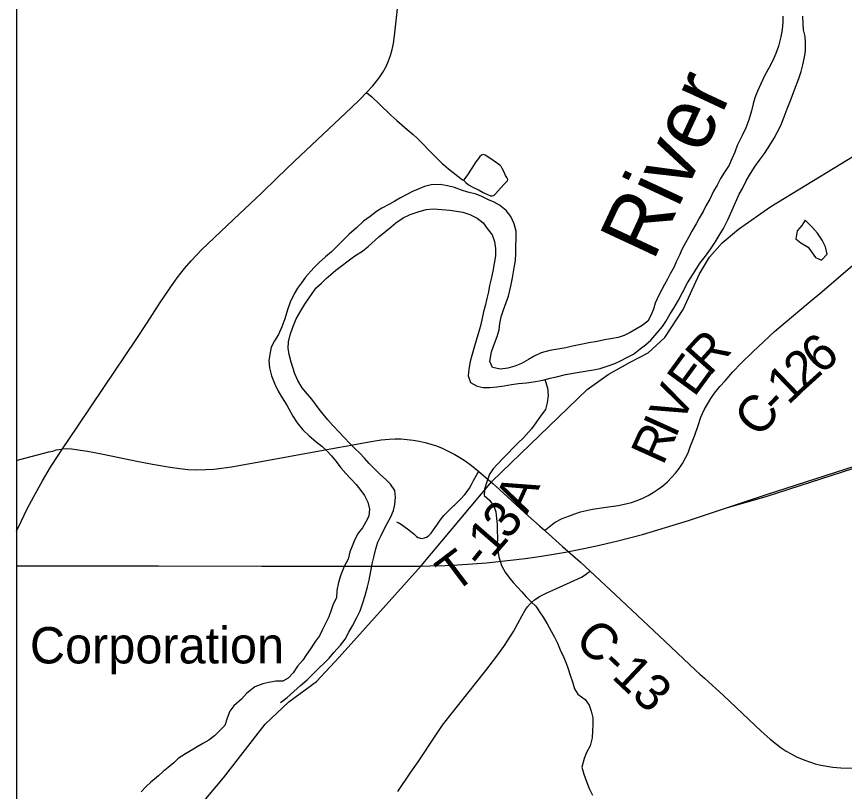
# Model space of a CAD drawing. Extents: x 0 to 34, y 0 to 22.
# Drawn here: x 2.1 to 3.389, y 14.854 to 16.061 of the extents above; entities that cross this region are included whole.
import ezdxf

# ---------------------------------------------------------------- set-up
doc = ezdxf.new("R2010")
doc.units = 0
for name, color, linetype in [('GM_X_Corporation', 7, 'Continuous'), ('GM_X_County_Road', 7, 'Continuous'), ('GM_X_County_Road_Text', 7, 'Continuous'), ('GM_X_Major_River', 7, 'Continuous'), ('GM_X_Minor_Lake', 7, 'Continuous'), ('GM_X_Minor_River', 7, 'Continuous'), ('GM_X_Minor_River_Text', 7, 'Continuous'), ('GM_X_Rail_Line', 7, 'Continuous'), ('GM_X_Rail_Line_Text', 7, 'Continuous'), ('GM_X_State_Route', 7, 'Continuous'), ('GM_X_Township_Road', 7, 'Continuous'), ('GM_X_Township_Road_Text', 7, 'Continuous'), ('SH_Data', 7, 'Continuous')]:
    doc.layers.add(name, color=color, linetype=linetype)

msp = doc.modelspace()

# ---------------------------------------------------------------- linework, layer by layer
at = {"layer": 'GM_X_Corporation'}
for points in [[(2.1, 20.7089), (2.1, 14.1)], [(2.1, 16.8894), (2.1, 14.1)]]:
    msp.add_lwpolyline(points, dxfattribs=at)
at = {"layer": 'GM_X_County_Road'}
for points in [[(3.161, 15.4241), (3.1655, 15.4373), (3.1705, 15.4485), (3.1761, 15.4586), (3.1811, 15.4662), (3.1867, 15.4748), (3.1948, 15.4849), (3.2031, 15.494), (3.2153, 15.508), (3.2282, 15.5214), (3.2461, 15.5387), (3.2801, 15.5704), (3.2965, 15.5846), (3.3322, 15.6145), (3.3537, 15.6322), (3.4055, 15.6768)], [(2.9221, 15.2611), (2.9238, 15.2624), (2.9342, 15.2704), (2.9387, 15.2736), (2.9495, 15.2794), (2.9606, 15.2834), (2.9693, 15.2868), (2.9782, 15.2897), (2.9873, 15.292), (2.9965, 15.2938), (3.018, 15.297), (3.0364, 15.2997), (3.0486, 15.3021), (3.0575, 15.3045), (3.0663, 15.3075), (3.0748, 15.3111), (3.0831, 15.3152), (3.0911, 15.3198), (3.0989, 15.3249), (3.1062, 15.3305), (3.1132, 15.3366), (3.1198, 15.343), (3.1261, 15.3499), (3.1318, 15.3571), (3.1366, 15.365), (3.1417, 15.3741), (3.1457, 15.3817), (3.1488, 15.3908), (3.1559, 15.409), (3.161, 15.4241)], [(2.1717, 15.3879), (2.1783, 15.3883), (2.1856, 15.3878), (2.2106, 15.3842), (2.2321, 15.3802), (2.29, 15.3681), (2.3114, 15.3639), (2.3389, 15.3591), (2.3543, 15.357), (2.3667, 15.3558), (2.3791, 15.3553), (2.3946, 15.3556), (2.4069, 15.3563), (2.4193, 15.3576), (2.4346, 15.3599), (2.4867, 15.3692), (2.5602, 15.3826), (2.6521, 15.3994), (2.6676, 15.4017), (2.68, 15.4029), (2.6894, 15.4033), (2.6988, 15.4032), (2.7081, 15.4025), (2.7175, 15.4014), (2.7267, 15.3998), (2.7359, 15.3978), (2.7449, 15.3953), (2.7539, 15.3923), (2.7626, 15.3889), (2.7711, 15.385), (2.7823, 15.3792), (2.7903, 15.3745), (2.7982, 15.3693), (2.8082, 15.3618), (2.8195, 15.3526)], [(2.1, 15.3698), (2.1053, 15.3713), (2.1503, 15.3833), (2.1565, 15.3845), (2.1617, 15.3861), (2.17, 15.3876), (2.1717, 15.3879)], [(2.8195, 15.3526), (2.8203, 15.352), (2.8416, 15.3337), (2.8462, 15.3296), (2.8967, 15.2834), (2.9144, 15.2682), (2.9221, 15.2611)], [(2.9221, 15.2611), (2.9235, 15.2599), (2.9499, 15.2356), (2.9779, 15.2112), (2.993, 15.1972)], [(2.993, 15.1972), (3.0325, 15.1605), (3.1005, 15.0966), (3.1571, 15.0433), (3.1636, 15.0368), (3.1708, 15.0309), (3.2006, 15.0037), (3.2595, 14.9483), (3.2734, 14.9358), (3.2829, 14.9279), (3.2904, 14.9224), (3.2982, 14.9173), (3.3062, 14.9127), (3.3145, 14.9085), (3.3258, 14.9035), (3.3345, 14.9003), (3.3434, 14.8976), (3.3524, 14.8954), (3.3615, 14.8936), (3.3707, 14.8923), (3.3831, 14.8913), (3.4048, 14.8905)]]:
    msp.add_lwpolyline(points, dxfattribs=at)
at = {"layer": 'GM_X_Major_River'}
for points in [[(2.8346, 15.6325), (2.832, 15.6222), (2.8294, 15.6108), (2.8272, 15.6012), (2.825, 15.5913), (2.8228, 15.5814), (2.8202, 15.5723), (2.8164, 15.5601), (2.812, 15.5441), (2.8087, 15.5334), (2.8061, 15.5239), (2.8039, 15.5121), (2.8032, 15.5015), (2.8067, 15.4912), (2.817, 15.4856), (2.8265, 15.4834), (2.8367, 15.4834), (2.8477, 15.4843), (2.8591, 15.4859), (2.8705, 15.4878), (2.8815, 15.4894), (2.8937, 15.4906), (2.9081, 15.4926), (2.9195, 15.495), (2.9308, 15.4981), (2.9426, 15.5005), (2.9547, 15.5036), (2.976, 15.5075), (2.9885, 15.5091), (2.998, 15.5107), (3.0086, 15.513), (3.0211, 15.5169), (3.0313, 15.5208), (3.0404, 15.525), (3.0514, 15.5304), (3.0605, 15.5354), (3.0707, 15.5435), (3.0794, 15.5496), (3.0877, 15.5569), (3.0967, 15.568), (3.1054, 15.5783), (3.1107, 15.5863), (3.1174, 15.5981), (3.1231, 15.6069), (3.1306, 15.6195), (3.1369, 15.6313), (3.1444, 15.6462), (3.1531, 15.6592), (3.1644, 15.6775), (3.1726, 15.6878), (3.1802, 15.6989), (3.1877, 15.7096), (3.1941, 15.7199), (3.2005, 15.731), (3.208, 15.7455), (3.2136, 15.7584), (3.2192, 15.7714), (3.2248, 15.7844), (3.23, 15.7931), (3.236, 15.805), (3.2424, 15.8164), (3.2499, 15.8282), (3.2567, 15.8374), (3.2642, 15.8477), (3.2729, 15.8607), (3.2796, 15.8718), (3.2849, 15.8813), (3.2898, 15.8916), (3.295, 15.9046), (3.2998, 15.9175), (3.3062, 15.9328), (3.311, 15.9469), (3.3177, 15.9648), (3.3215, 15.9754), (3.3241, 15.9857), (3.3266, 15.9979), (3.3281, 16.0078), (3.3284, 16.02), (3.3279, 16.0299), (3.3252, 16.0401), (3.3244, 16.0504), (3.3243, 16.0618)], [(3.2931, 16.0616), (3.2932, 16.0521), (3.2921, 16.041), (3.2899, 16.0292), (3.2862, 16.0151), (3.2821, 16.0037), (3.2773, 15.9926), (3.2717, 15.9816), (3.2649, 15.9698), (3.2585, 15.9564), (3.2533, 15.945), (3.2492, 15.9343), (3.2466, 15.9252), (3.2444, 15.9141), (3.2399, 15.9), (3.2355, 15.8878), (3.2295, 15.876), (3.222, 15.8604), (3.2182, 15.8497), (3.2138, 15.8394), (3.2093, 15.8295), (3.2021, 15.8188), (3.1961, 15.8089), (3.1905, 15.7986), (3.1852, 15.789), (3.1792, 15.7765), (3.1732, 15.7665), (3.1687, 15.7574), (3.1627, 15.7471), (3.1582, 15.7383), (3.1511, 15.7269), (3.1459, 15.7169), (3.1414, 15.7085), (3.1365, 15.6994), (3.132, 15.6895), (3.1275, 15.6803), (3.1238, 15.6712), (3.1178, 15.6605), (3.1133, 15.6521), (3.1088, 15.6437), (3.1005, 15.6284), (3.0941, 15.6147), (3.0915, 15.6052), (3.0874, 15.5953), (3.0826, 15.5869), (3.0742, 15.58), (3.0652, 15.5746), (3.0553, 15.5692), (3.0459, 15.5646), (3.0364, 15.5615), (3.0246, 15.5591), (3.0151, 15.5576), (3.0041, 15.5552), (2.9912, 15.5529)], [(2.9912, 15.5529), (2.9783, 15.5505), (2.9654, 15.5477), (2.9552, 15.5454), (2.9396, 15.5426), (2.9302, 15.5411), (2.9169, 15.5372), (2.9059, 15.5322), (2.8972, 15.5268), (2.8859, 15.5206), (2.8756, 15.5164), (2.865, 15.5133), (2.8532, 15.5117), (2.8411, 15.5146), (2.8368, 15.5237), (2.8394, 15.539), (2.8439, 15.5519), (2.8483, 15.563), (2.8513, 15.5733), (2.8524, 15.5828), (2.8546, 15.5934), (2.8579, 15.6045), (2.862, 15.6159), (2.8658, 15.6254), (2.8694, 15.641), (2.872, 15.6544), (2.8749, 15.6696), (2.8768, 15.6814), (2.8775, 15.692), (2.8774, 15.7035), (2.8777, 15.7156), (2.8776, 15.727), (2.8749, 15.7384), (2.8695, 15.7494), (2.8622, 15.7589), (2.8519, 15.7672), (2.8435, 15.7721), (2.8347, 15.7758), (2.8244, 15.7807), (2.8153, 15.7844), (2.8027, 15.7878), (2.7928, 15.7907), (2.7818, 15.7949), (2.7711, 15.7974), (2.7593, 15.7993), (2.7453, 15.7992), (2.735, 15.7965), (2.7252, 15.7922), (2.7165, 15.7884), (2.7078, 15.7841), (2.6979, 15.7787), (2.6888, 15.7734), (2.6805, 15.7687), (2.6688, 15.7626), (2.6605, 15.7576), (2.6503, 15.7499), (2.6404, 15.7422), (2.6291, 15.7319), (2.6178, 15.722), (2.6076, 15.712), (2.5985, 15.7028), (2.5902, 15.6948), (2.5808, 15.6871), (2.571, 15.6779), (2.5627, 15.6699), (2.5499, 15.655), (2.5435, 15.6466), (2.5374, 15.6382), (2.5322, 15.629), (2.5262, 15.6161), (2.5217, 15.6042), (2.5176, 15.5901), (2.5132, 15.5776), (2.5079, 15.5661), (2.5015, 15.5562), (2.4963, 15.5463), (2.4941, 15.5349), (2.493, 15.5254), (2.4939, 15.514), (2.497, 15.5018), (2.502, 15.4885), (2.5074, 15.4775), (2.5136, 15.4673), (2.5209, 15.456), (2.5301, 15.4389), (2.537, 15.4283), (2.5458, 15.4173), (2.5558, 15.4083), (2.5661, 15.3992), (2.5752, 15.3921), (2.5833, 15.3849), (2.5902, 15.3769), (2.5974, 15.3679), (2.6051, 15.3584), (2.6128, 15.3497), (2.62, 15.3418), (2.6288, 15.3323), (2.6361, 15.3229), (2.6419, 15.3153), (2.6469, 15.3047), (2.6496, 15.2937)], [(2.5111, 14.9928), (2.5213, 15.0009), (2.5315, 15.0101), (2.5421, 15.0193), (2.5523, 15.0284), (2.5617, 15.0376), (2.5719, 15.0472), (2.5787, 15.0541), (2.5866, 15.0617), (2.5942, 15.0705), (2.6044, 15.082), (2.6115, 15.0916), (2.6175, 15.1022), (2.6231, 15.1122), (2.6295, 15.1244), (2.6348, 15.1358), (2.6392, 15.148), (2.6429, 15.1594), (2.6463, 15.1728), (2.6489, 15.1834), (2.6514, 15.1975), (2.654, 15.2108), (2.6566, 15.2215), (2.6595, 15.2321), (2.6625, 15.2424), (2.6674, 15.2527), (2.6722, 15.2626), (2.6771, 15.2718), (2.6827, 15.2821), (2.6869, 15.2916), (2.6891, 15.3012), (2.6901, 15.3126), (2.6889, 15.3228), (2.682, 15.3327), (2.6744, 15.3406), (2.6656, 15.3485), (2.656, 15.358), (2.6491, 15.3648), (2.6415, 15.3731), (2.6342, 15.381), (2.6269, 15.3886), (2.6185, 15.3969), (2.6105, 15.4052), (2.6024, 15.4139), (2.5925, 15.4241), (2.5845, 15.4332), (2.5776, 15.4419), (2.571, 15.4498), (2.5653, 15.4574), (2.5595, 15.4653), (2.553, 15.4729), (2.5446, 15.4831), (2.5381, 15.4941), (2.5334, 15.5047), (2.5276, 15.5229), (2.5245, 15.5347), (2.5229, 15.5446), (2.5236, 15.5544), (2.5262, 15.5655), (2.5299, 15.5773), (2.5355, 15.5903), (2.5426, 15.6029), (2.5486, 15.6132), (2.5543, 15.6216), (2.5603, 15.6296), (2.5667, 15.6384), (2.5746, 15.6456), (2.5818, 15.6529), (2.5893, 15.6594), (2.5973, 15.6659), (2.6056, 15.6725), (2.6162, 15.6805), (2.6268, 15.6882), (2.6385, 15.6959), (2.6472, 15.7028), (2.6642, 15.7181), (2.6747, 15.7269), (2.683, 15.7338), (2.6906, 15.7399), (2.7019, 15.7476), (2.7129, 15.753), (2.7254, 15.7569), (2.7376, 15.7604), (2.7486, 15.7616), (2.7619, 15.7605), (2.7744, 15.7594), (2.7847, 15.758), (2.795, 15.7562), (2.8056, 15.7528), (2.817, 15.7472), (2.8262, 15.7396), (2.8327, 15.7309), (2.8404, 15.7211), (2.8443, 15.7105), (2.8459, 15.6998), (2.8459, 15.6884), (2.8437, 15.6766), (2.8416, 15.6644), (2.839, 15.6526), (2.8364, 15.642), (2.8346, 15.6325)], [(2.6496, 15.2937), (2.6486, 15.283), (2.6437, 15.2743), (2.6384, 15.2647), (2.6316, 15.2563), (2.6264, 15.2468), (2.6227, 15.2365), (2.6189, 15.2277), (2.6163, 15.2163), (2.6103, 15.2045), (2.6051, 15.1915), (2.601, 15.1797), (2.5988, 15.1675), (2.5981, 15.1561), (2.5929, 15.1458), (2.5899, 15.1367), (2.5862, 15.1264), (2.5809, 15.1161), (2.5761, 15.1065), (2.5716, 15.0966), (2.5652, 15.0886), (2.5577, 15.0764), (2.5516, 15.0676), (2.5456, 15.0588), (2.5373, 15.0493), (2.5306, 15.0393), (2.523, 15.0309), (2.5143, 15.0263), (2.5037, 15.0259), (2.4927, 15.0239), (2.4832, 15.0219), (2.4711, 15.0173), (2.4579, 15.0069), (2.4503, 14.9981), (2.4382, 14.9878), (2.4318, 14.9794), (2.4277, 14.9687), (2.4244, 14.9569), (2.415, 14.9477), (2.4082, 14.9408), (2.3991, 14.9343), (2.3908, 14.9293), (2.3813, 14.924), (2.3719, 14.9182), (2.3628, 14.9128), (2.3518, 14.9059), (2.345, 14.899), (2.3359, 14.8917), (2.3284, 14.8852), (2.3212, 14.8787), (2.3088, 14.8687), (2.302, 14.8619), (2.294, 14.8538)]]:
    msp.add_lwpolyline(points, dxfattribs=at)
at = {"layer": 'GM_X_Minor_Lake'}
for points in [[(3.3276, 15.7439), (3.3227, 15.7355), (3.3152, 15.7271), (3.3134, 15.715), (3.321, 15.7085), (3.3322, 15.7019)], [(3.3322, 15.7019), (3.3378, 15.6946), (3.344, 15.6859), (3.3531, 15.6817), (3.3618, 15.6909), (3.3594, 15.7023), (3.3541, 15.7126), (3.3471, 15.7239), (3.3391, 15.7326), (3.3276, 15.7439)]]:
    msp.add_lwpolyline(points, dxfattribs=at)
at = {"layer": 'GM_X_Minor_River'}
msp.add_lwpolyline([(2.9222, 15.4958), (2.9264, 15.4829), (2.9276, 15.4711), (2.9262, 15.4597), (2.9236, 15.449), (2.9168, 15.4402), (2.9085, 15.4284), (2.9018, 15.4188), (2.8893, 15.4051), (2.881, 15.397), (2.8727, 15.389), (2.8652, 15.3813), (2.858, 15.3741), (2.8486, 15.3641), (2.8418, 15.3565), (2.8361, 15.3485), (2.832, 15.3367), (2.8287, 15.3249), (2.828, 15.3153), (2.8364, 15.3078), (2.8433, 15.2987), (2.8464, 15.2896), (2.8473, 15.2793), (2.8481, 15.2698), (2.8481, 15.26), (2.8486, 15.2497), (2.8483, 15.2391), (2.8491, 15.2296), (2.8507, 15.2197), (2.855, 15.206), (2.8607, 15.1958), (2.8665, 15.1878), (2.8734, 15.1795), (2.8799, 15.1723), (2.8868, 15.1652), (2.8933, 15.1576), (2.901, 15.1497), (2.9082, 15.1429), (2.9144, 15.1342), (2.9201, 15.1255), (2.9263, 15.1156), (2.9324, 15.1042), (2.9374, 15.0948), (2.9424, 15.0853), (2.9463, 15.0747), (2.9513, 15.0641), (2.9556, 15.0542), (2.9587, 15.0451), (2.9618, 15.0352), (2.9653, 15.025), (2.9687, 15.0144), (2.9737, 15.0057), (2.9852, 14.9974), (2.9913, 14.9887), (2.9948, 14.9792), (2.9972, 14.9689), (2.9972, 14.9583), (2.9969, 14.9488), (2.9959, 14.9381), (2.9929, 14.9252), (2.9873, 14.9149), (2.9839, 14.9057), (2.9798, 14.892), (2.983, 14.8814), (2.9872, 14.87), (2.9915, 14.859), (2.9965, 14.8488)], dxfattribs=at)
at = {"layer": 'GM_X_Rail_Line'}
for points in [[(2.7297, 15.2056), (2.8397, 15.3372), (2.9885, 15.4804), (3.0212, 15.5034), (3.0552, 15.5228), (3.0833, 15.5374), (3.1093, 15.5614), (3.1376, 15.6046), (3.1635, 15.6602), (3.1788, 15.6862), (3.1987, 15.7084), (3.224, 15.7301), (3.2743, 15.765), (3.5468, 15.9313), (3.5769, 15.9577), (3.6509, 16.0195), (3.6692, 16.0362), (3.6936, 16.0627)], [(3.2088, 15.2971), (3.2684, 15.3142), (3.4536, 15.3739), (3.5291, 15.3985), (3.8359, 15.4986), (4.0815, 15.5782), (4.2209, 15.6235), (4.4575, 15.6975), (4.6896, 15.7766), (4.9157, 15.8481), (5.2297, 15.9517), (5.4604, 16.0265), (5.5567, 16.0607)], [(2.1, 15.2057), (2.3212, 15.2055), (2.4818, 15.2052), (2.7299, 15.2051), (2.7433, 15.2055), (2.7673, 15.2064), (2.7866, 15.2072), (2.8099, 15.2088), (2.8318, 15.2105), (2.8688, 15.2143), (2.8917, 15.2171), (2.9174, 15.2209), (2.9545, 15.227), (2.9856, 15.2332), (3.0077, 15.2379), (3.0362, 15.2445), (3.0743, 15.2545), (3.1463, 15.2765), (3.2677, 15.3166), (3.4529, 15.3763)], [(2.2464, 14.1), (2.2668, 14.1719), (2.2701, 14.2246), (2.2577, 14.2692), (2.243, 14.3024), (2.2171, 14.3346), (2.1851, 14.3637), (2.1516, 14.3933), (2.1319, 14.4344), (2.1227, 14.467), (2.1207, 14.5129), (2.1301, 14.5585), (2.1526, 14.5946), (2.1807, 14.6303), (2.2177, 14.682), (2.2745, 14.7402), (2.3385, 14.787), (2.3897, 14.8368), (2.4224, 14.8755), (2.4871, 14.9592), (2.5237, 14.9937), (2.567, 15.0258), (2.6022, 15.0634), (2.7297, 15.2056)]]:
    msp.add_lwpolyline(points, dxfattribs=at)
at = {"layer": 'GM_X_State_Route'}
msp.add_lwpolyline([(2.1, 15.2598), (2.1071, 15.2749), (2.1166, 15.2944), (2.1267, 15.3137), (2.1404, 15.3381), (2.1531, 15.3594), (2.1648, 15.3777), (2.1717, 15.3879), (2.1944, 15.4215), (2.236, 15.4835), (2.2862, 15.5583), (2.3034, 15.5843), (2.3238, 15.6155), (2.3394, 15.6387), (2.3503, 15.6539), (2.3617, 15.6686), (2.3716, 15.6805), (2.3799, 15.6896), (2.3887, 15.6984), (2.4473, 15.754), (2.4811, 15.7862), (2.5059, 15.8098), (2.5329, 15.8356), (2.5508, 15.8528), (2.6207, 15.9191), (2.6342, 15.9321), (2.6447, 15.9426), (2.6547, 15.9531), (2.6608, 15.9608), (2.6656, 15.9671), (2.6706, 15.975), (2.6752, 15.9833), (2.679, 15.9918), (2.6822, 16.0006), (2.6847, 16.0096), (2.6867, 16.0188), (2.6885, 16.0311), (2.6984, 16.1208)], dxfattribs=at)
at = {"layer": 'GM_X_Township_Road'}
for points in [[(2.6447, 15.9426), (2.6529, 15.9359), (2.665, 15.9246), (2.6828, 15.9074), (2.6919, 15.8993), (2.7081, 15.885), (2.7173, 15.8776), (2.7242, 15.8712), (2.735, 15.86), (2.7394, 15.8553), (2.7573, 15.8376), (2.7633, 15.8319), (2.7652, 15.8303), (2.7724, 15.8239), (2.7945, 15.807), (2.796, 15.806)], [(2.8646, 15.8075), (2.8633, 15.8105), (2.8612, 15.8136), (2.859, 15.8187), (2.8561, 15.8246), (2.8544, 15.8276), (2.8525, 15.8297), (2.849, 15.8324), (2.8434, 15.8357), (2.8323, 15.8437), (2.8296, 15.8454), (2.8267, 15.846), (2.8237, 15.8453), (2.8214, 15.8433), (2.8192, 15.8402), (2.8151, 15.8346), (2.8089, 15.8251), (2.8008, 15.8131), (2.796, 15.806)], [(2.796, 15.806), (2.7994, 15.8026), (2.8037, 15.7991), (2.8105, 15.7952), (2.8202, 15.7905), (2.8266, 15.7871), (2.8377, 15.7821), (2.8406, 15.7816), (2.8431, 15.7824), (2.8454, 15.7847), (2.8534, 15.7938), (2.8597, 15.8006), (2.8642, 15.805), (2.8646, 15.8075)], [(2.7818, 15.3003), (2.7915, 15.3098), (2.7978, 15.3167), (2.8017, 15.3216), (2.8052, 15.3268), (2.8083, 15.3323), (2.8113, 15.3386), (2.8182, 15.3503), (2.8195, 15.3526)], [(2.6916, 15.2743), (2.6942, 15.2732), (2.6968, 15.2717), (2.6992, 15.2701), (2.7087, 15.2634), (2.7183, 15.2557), (2.7225, 15.2515), (2.7252, 15.2497), (2.7284, 15.2487), (2.7317, 15.2485), (2.7349, 15.2491), (2.738, 15.2502), (2.7409, 15.2521), (2.7432, 15.2543), (2.7453, 15.2567), (2.749, 15.2615), (2.7541, 15.2692), (2.7593, 15.2768), (2.7651, 15.284), (2.7693, 15.2884), (2.7804, 15.299), (2.7818, 15.3003)], [(2.6937, 14.8544), (2.7128, 14.8827), (2.725, 14.9007), (2.7526, 14.9421), (2.7633, 14.9574), (2.7745, 14.9723), (2.8306, 15.0429), (2.8477, 15.065), (2.8586, 15.0801), (2.8655, 15.0904), (2.8735, 15.1036), (2.887, 15.1286), (2.892, 15.1366), (2.8957, 15.1417), (2.8996, 15.1464), (2.9017, 15.1486), (2.9064, 15.1527), (2.9089, 15.1545), (2.9142, 15.1579), (2.9254, 15.1636), (2.9396, 15.1701), (2.968, 15.1826), (2.9797, 15.1883), (2.985, 15.1915), (2.9901, 15.1951), (2.993, 15.1972)]]:
    msp.add_lwpolyline(points, dxfattribs=at)
at = {"layer": 'SH_Data'}
msp.add_line((2.1, 20.9), (2.1, 14.1), dxfattribs=at)

# ---------------------------------------------------------------- texts
at = {"layer": 'GM_X_County_Road_Text'}
for s, height, rotation, p in [('R', 0.0568, 48.0414, (3.179, 15.5001)), ('6', 0.0568, 40.6831, (3.3519, 15.502)), ('E', 0.0568, 53.8797, (3.1549, 15.467)), ('2', 0.0568, 42.0936, (3.3262, 15.4787)), ('1', 0.0568, 43.9622, (3.3014, 15.4548)), ('V', 0.0568, 64.8964, (3.1351, 15.4242)), ('C', 0.0568, 51.2122, (3.2572, 15.403)), ('-', 0.0568, 45.977, (3.2855, 15.4384)), ('I', 0.0568, 65.6271, (3.1256, 15.4031)), ('R', 0.0568, 65.6277, (3.1063, 15.3606)), ('C-13', 0.05682, 316.7057, (2.9665, 15.087))]:
    msp.add_text(s, height=height, rotation=rotation, dxfattribs=at).set_placement(p)
at = {"layer": 'GM_X_Minor_River_Text'}
msp.add_text('River', height=0.09475, rotation=65.0032, dxfattribs=at).set_placement((3.091, 15.6784))
at = {"layer": 'GM_X_Rail_Line_Text'}
msp.add_text('Corporation', height=0.056629, rotation=0, dxfattribs=at).set_placement((2.1208, 15.0537))
at = {"layer": 'GM_X_Township_Road_Text'}
for s, rotation, p in [('A', 65.6114, (2.8949, 15.2848)), ('3', 51.6766, (2.8653, 15.2445)), ('1', 49.0346, (2.8406, 15.2158)), ('T', 37.0885, (2.7815, 15.162)), ('-', 50.9834, (2.8262, 15.1981))]:
    msp.add_text(s, height=0.0568, rotation=rotation, dxfattribs=at).set_placement(p)

doc.saveas('drawing.dxf')
